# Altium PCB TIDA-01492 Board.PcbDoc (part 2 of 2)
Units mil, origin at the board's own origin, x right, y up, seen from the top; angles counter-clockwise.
Board outline 4930.03 x 2625.03 mil, 4 copper layers (Top Layer, Signal Layer 1, Signal Layer 2, Bottom Layer), stack 38.4 mil thick; 141 components, 49 nets, 383 pads, 426 vias.
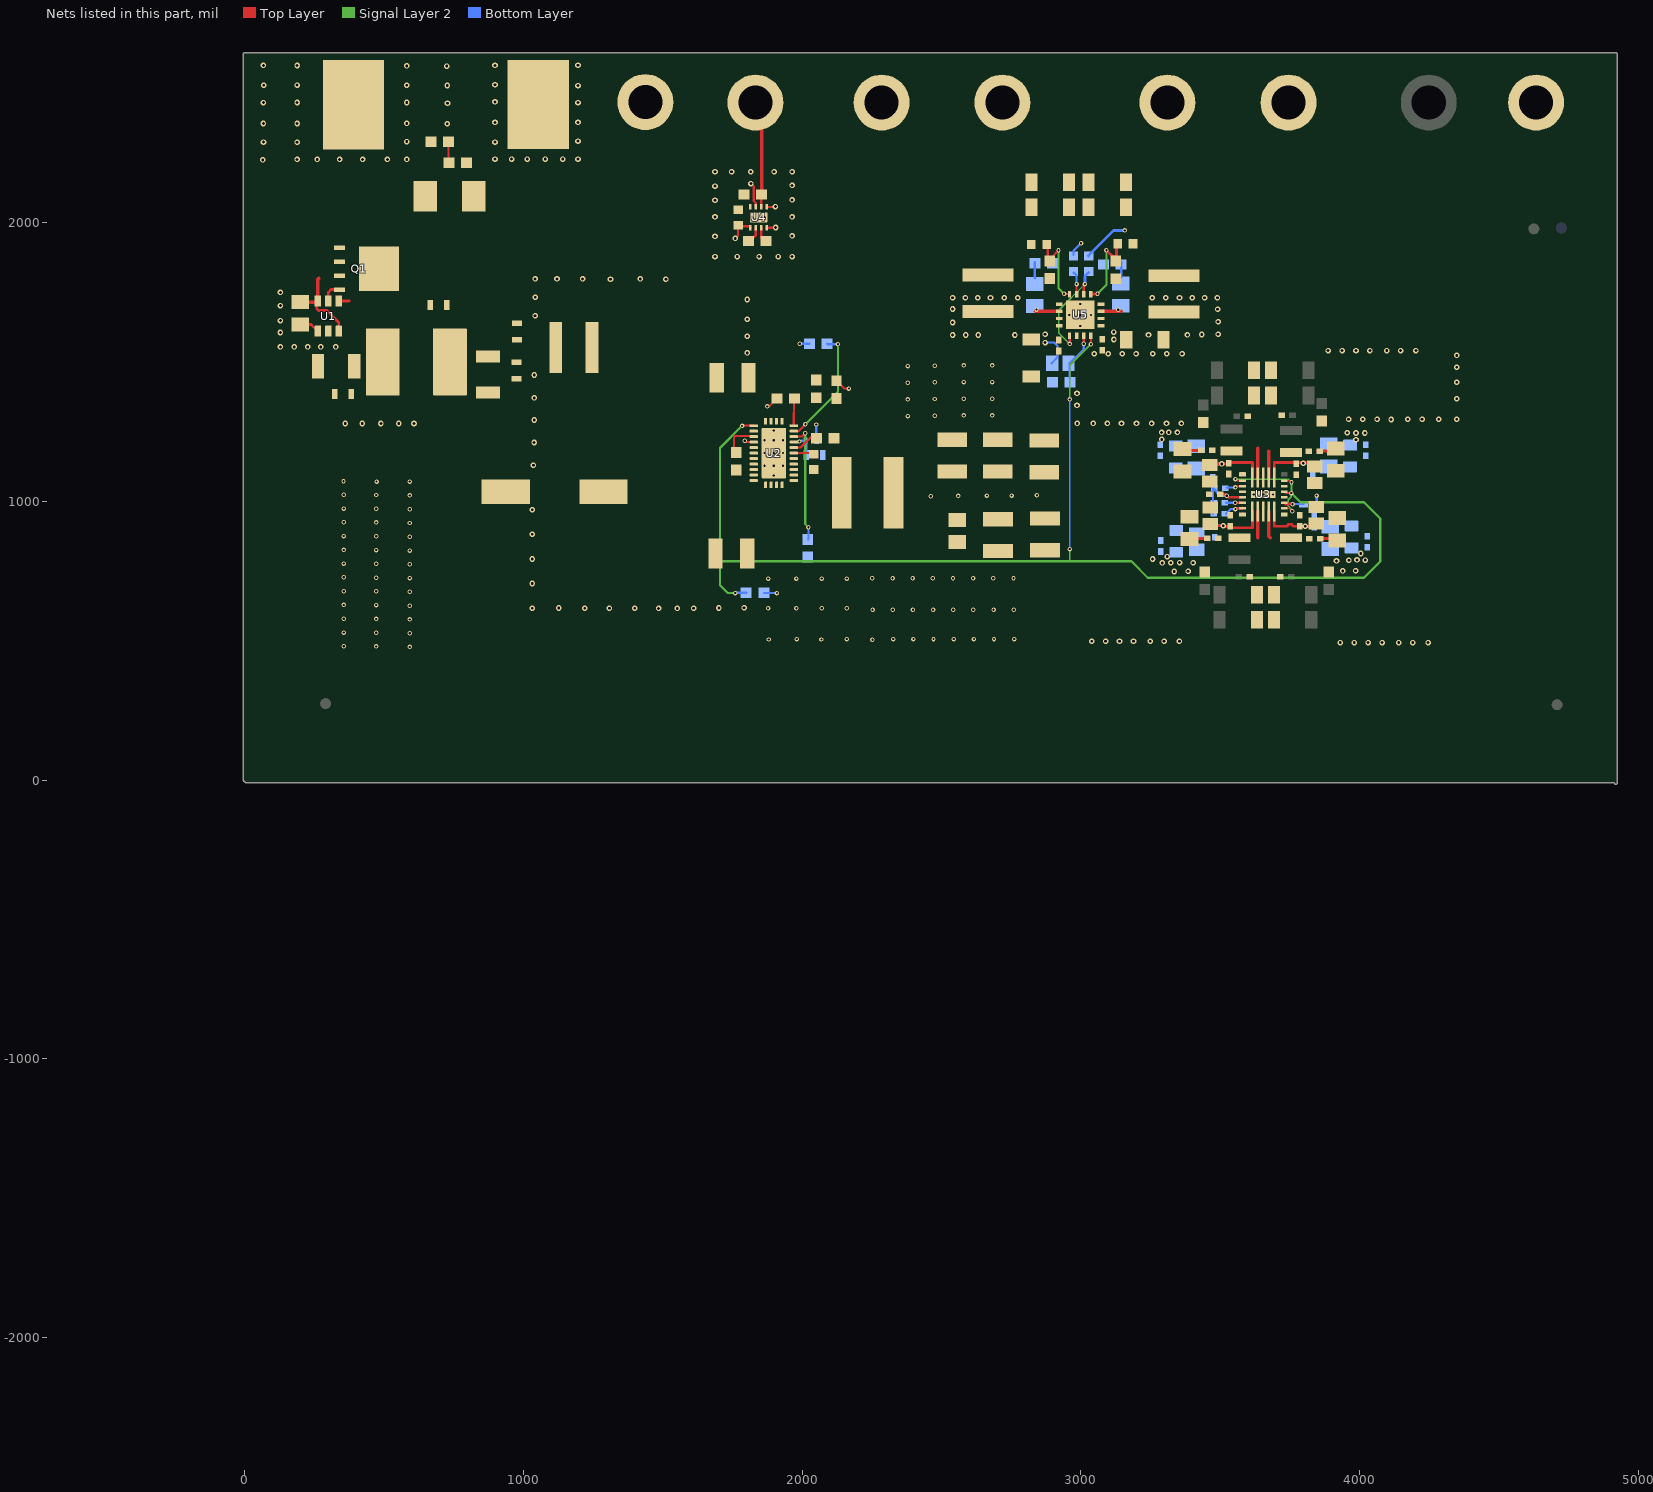
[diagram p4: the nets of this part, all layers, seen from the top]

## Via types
v1: diameter 20, hole 10, Top Layer to Bottom Layer, 270 vias
v2: diameter 16, hole 8, Top Layer to Bottom Layer, 134 vias
v3: diameter 19.68, hole 7.87, Top Layer to Bottom Layer, 21 vias
v4: diameter 16/16/16/16 (per signal layer), hole 8, Top Layer to Bottom Layer, 1 vias

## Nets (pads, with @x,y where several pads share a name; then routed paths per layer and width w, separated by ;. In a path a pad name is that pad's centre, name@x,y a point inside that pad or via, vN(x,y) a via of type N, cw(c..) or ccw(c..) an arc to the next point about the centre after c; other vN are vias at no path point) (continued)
1.2V: 1.2V.1 C56.1 C57.1 L11.2 R14.2
1.8V: 1.8V.1 C54.1 C55.1 L10.2 R11.1 R12.2 | length 169.2
  Bottom Layer w10: R11.1@3028,1880.56 3028,1882.5 3118,1972.5 v2(3158,1972.5)
5V_CAN: 5V.1 C47.1 U4.6 | length 384.7
  Top Layer w10: U4.6@1853.69,2056.75 1853.69,2100.19 C47.1@1855.35,2101.85
  Top Layer w13: 5V.1@1832.5,2431 1854.84,2408.66 C47.1@1854.84,2101.35
AGND: CSS.2 NTGND.2 RFBB.1 U2.19 | length 120.9
  Top Layer w8: v4(1794.5,1217.5) 1799.13,1212.87 U2.19@1826.65,1212.87 ; v2@1878.5,1344.5 v2(1875,1341) 1881.99,1341 RFBB.1@1910.19,1369.2
  Bottom Layer w8: v2(1991.5,1566) CSS.2@2026.5,1566
BIAS: Cbias1.1 Rbias1.1 U2.8 | length 63.3
  Bottom Layer w8: v2(1990.5,1215) 1993.5,1218 Rbias1.1@2012.5,1218 2015,1215.5 Cbias1.1@2015,1179
FB: CFF.2 RFBB.2 RFBT.1 U2.11 | length 97.1
  Top Layer w8: U2.11@1970.35,1271.93 RFBB.2@1970.5,1369
FB1_: R12.1 R15.2 U5.5 | length 285.6
  Top Layer w10: U5.5@3036.14,1744.01 3059.01,1744.01 v2(3060,1745) ; v2(3092,1901) 3114.5,1878.5 3129,1878.5 3128.5,1878.99 R12.1@3128.5,1924
  Signal Layer 2 w8: v2(3060,1745) 3092,1777 v2(3092,1901)
FB2_: R14.1 R17.2 U5.8 | length 277.9
  Top Layer w8: R14.1@2881.5,1922 2881.5,1877 2882,1876.5 2895.5,1876.5 v2(2920,1901) ; v2(2940,1745) 2940.99,1744.01 U5.8@2959.36,1744.01
  Signal Layer 2 w8: v2(2920,1901) 2920,1765 v2(2940,1745)
GATEDRIVE: Q1.4 U1.5 | length 74.6
  Top Layer w10: U1.5@300,1719.13 300,1750 310,1760 Q1.4@339.57,1760
GND: C0_2.1 C0_3.2 C1.2 C1_2.1 C1_3.2 C2.2 C2_2.1 C2_3.2 C3.2 C3_2.1 C3_3.2 C4.2 C5.1 C6.2 C7.1 C8.2 C10.1 C18.2 C19.2 C20.1 C21.2 C22.2 C23.1 C26.2 C27.2 C28.1 C29.2 C30.2 C31.1 C32.2 C33.2 C34.1 C35.2 C36.2 C37.2 C38.1 C39.2 C40.2 C41.2 C42.2 C43.2 C44.2 C45.2 C47.2 C48.2 C49.1 C50.2 C51.1 C52.2 C53.2 C54.2 C55.2 C56.2 C57.2 C58.2 Cbias1.2 Cbulk1.2 CF1.2 CF2.2 CI1.1 CI2.1 CI3.1 CO1.2 CO2.2 CO3.2 CO4.2 CO5.2 CO.1 CVCC.2 D1.2 GND1.1 GND2.1 GND3.1 GND4.1 GND_.1 NTGND.1 R1.1 R2.1 R3.1 R4.1 R15.1 R17.1 RT.2 U1.2 U2.12 U2.13 U2.14 U2.15 U2.17 U2.23 U2.24 U2.25 U2.26 U2.27 U2.28 U2.29 U2.30 U2.31 U3.1 U3.4 U3.6 U3.11 U3.14 U3.17 U3.21 U3.24 U3.27 U4.8 U4.9@1843.84,2019.35 U5.4 U5.9 U5.14 U5.17 | length 2.3
  Top Layer w10: U3.21@3580.2,953.15 U3.21@3580.2,955.43
  other v1: 3931,493.5 3981,493.5 4031,493.5 4081,493.5 4141,493.5 4191,493.5 4246,493.5 3039,498 3089,498 3139,498 3189,498 3249,498 3299,498 3354,498 1308.5,616.5 1399.5,616.5 1485,616 1552,616 1032,617 1220,617 1610.5,617 1126.5,617.5 1701.5,617.5 1792,618.5 1032,705.5 3335.5,748.5 3385,749.5 3940,750.5 3986,751 3403,780 3917.5,786.5 1032,793.5 3257.5,793.5 1032,882 1032,970 1036,1129.5 1038.5,1211.5 360.5,1279.5 421.5,1279.5 488.5,1279.5 553,1279.5 607.5,1279.5 2987,1280 3044.5,1280 3095.5,1280 3146,1280 3200,1280 3254,1280 3307.5,1280 3361,1280 1039,1292 3961,1294.5 4012,1294.5 4063,1294.5 4113.5,1294 4173,1294.5 4224.5,1294.5 4284.5,1294.5 4349,1294.5 2986.5,1344.5 4349,1368.31 1039,1371.5 2986.5,1387.5 4349,1427.81 1039,1453.5 4349,1481.31 4349,1524 3048.5,1529.5 3098.5,1529.5 3148.5,1529.5 3198.5,1529.5 3258.5,1529.5 3308.5,1529.5 3363.5,1529.5 1803.5,1533 3887.5,1541 3937.5,1541 3987.5,1541 4037.5,1541 4097.5,1541 4147.5,1541 4202.5,1541 128,1554.5 177.5,1554.5 226,1554.5 273,1554.5 327,1554.5 1803.5,1593 2540,1597 2587.5,1597 2632,1597 2763.5,1597 3243,1597.5 3382.5,1597.5 3434,1599 3492.5,1599.5 128,1606 2540,1642 3492.5,1645 128,1649 1803,1653.5 1042,1666 2540,1690.5 3491,1689.5 128,1702.5 1803,1724.5 2540,1730.5 2586,1730.5 2630,1730.5 2676,1730.5 2725.71,1730.5 2774,1730.5 3256.26,1730.57 3304.54,1730.57 3354.26,1730.57 3400.26,1730.57 3444.26,1730.57 3490.26,1730.57 1042.5,1732.5 128,1750 1042,1798.5 1120.5,1798.5 1212.5,1798.5 1312.5,1797.5 1419,1798.5 1511.5,1797.5 1687.5,1878.5 1767.5,1878.5 1845.5,1878.5 1914.5,1878.5 1964,1878.5 1687.5,1951 1964,1952.5 1687.5,2021 1964,2021 1687.5,2081 1964,2082 1687.5,2131.5 1964,2134 1687.5,2183 1747,2183 1815.5,2183 1899.5,2183 1964,2183 64.5,2225.5 898,2228.5 957.5,2228.5 1014,2228.5 1078.5,2228.5 1141,2228.5 1196,2228.5 67.5,2289.5 898,2289.5 1196,2293 726.5,2355 67,2356 898,2360 1196,2360 727.5,2429 67,2431 1196,2431 898,2433.5 726.5,2492.5 1196,2492 68,2493.5 898,2495 725,2562 67,2564.5 898,2564.5 1196,2565
  other v2: 592.5,478 355.5,480.5 472,479.5 1880,504.5 2069.5,504.5 2252.5,504 1980.5,506 2160.5,506 2327,506 2399.5,506 2471.5,506 2544,506 2616.5,506 2688.5,506 2761,506 592.5,527 472,529 355.5,529.5 592.5,576.5 472,578.5 355.5,579 2253,611 2325,611 2397.5,611 2470,611 2542,611 2614.5,611 2687,611 2759.5,611 1878,617 1979.5,617 2070.5,617 2160.5,617 592.5,626 355.5,628.5 472,628 592.5,675.5 355.5,678 472,677.5 1878.5,723 1979.5,723 2070.5,723 2160.5,723 2252,724 2324.5,724 2396.5,724 2469,724 2541.5,724 2613.5,724 2686,724 2758.5,724 592.5,725 472,726.5 355.5,727.5 592.5,774.5 472,776 355.5,777 592.5,823.5 355.5,826 472,825.5 592.5,873 472,875 355.5,875.5 592.5,922.5 472,924.5 355.5,925 592.5,972 355.5,974.5 472,974 592.5,1021.5 472,1023 355.5,1024 473,1071 592.5,1071 354.5,1072 2379,1306 2476,1307.5 2580,1308.5 2682.5,1308.5 2379,1366 2476,1367.5 2580,1368.5 2682.5,1368.5 2379,1426 2476,1427.5 2580,1428 2682.5,1428 2379,1485.5 2476,1487 2580,1488 2682.5,1488
  other v3: 3620.75,1025 3655,1025 3689.25,1025 1898.5,1092.79 1865.04,1127.83 1898.5,1127.83 1931.96,1127.83 1865.04,1173.5 1898.5,1173.5 1931.96,1173.5 1865.04,1219.17 1898.5,1219.17 1931.96,1219.17 1898.5,1254.21 2997.75,1629.84 2958.38,1669.21 2997.75,1669.21 3037.12,1669.21 2997.75,1708.58 1822.19,2019.35 1865.5,2019.35
NetC3_1: C3.1 C8.1 CF2.1 FB1.2 LF1.1
NetC9_2: C9.2 C10.2 | length 75.8
  Top Layer w8: C9.2@731.5,2290 731.5,2217.01 C10.2@733.5,2215
NetC11_2: C11.2 U1.1 | length 72.6
  Top Layer w10: C11.2@200,1635 238.46,1635 U1.1@262.6,1610.87
NetC16_2: C16.2 R1.2 | length 69.7
  Top Layer w6: R1.2@3905.5,1180.5 R1.2@3915,1190
  Top Layer w10: C16.2@3849.19,1180.5 R1.2@3905.5,1180.5
NetC17_2: C17.2 R2.2 | length 67.4
  Top Layer w10: C17.2@3855.49,867.09 3912.91,867.09 R2.2@3920,860
NetC24_2: C24.2 R3.2 | length 69.7
  Top Layer w10: R3.2@3365,1187.5 3369.5,1183 C24.2@3432.81,1183
NetC25_2: C25.2 R4.2 | length 65.1
  Top Layer w10: R4.2@3390,865 3392,867 C25.2@3454.31,867
NetC46_1: C46.1 U4.3 | length 59.5
  Top Layer w10: U4.3@1853.69,1981.94 1853.69,1946 C46.1@1870.34,1929.35
NetC46_2: C46.2 U4.2 | length 63.6
  Top Layer w10: C46.2@1807.35,1929.35 1834,1956 U4.2@1834,1981.94
NetC52_1: C52.1 R10.2 | length 54.5
  Bottom Layer w10: R10.2@3145,1805 C52.1@3145,1859.5
NetC58_1: C58.1 R16.1 | length 56.9
  Bottom Layer w10: C58.1@2835,1858.5 2835,1803 R16.1@2836,1802
NetCB_1: CB.1 U2.6 | length 60.7
  Top Layer w8: U2.6@1970.35,1173.5 CB.1@2031,1173.5
NetR5_2: R5.2 U3.16 | length 61.3
  Top Layer w6: v2(3555,1050) 3559.53,1054.53 U3.16@3580.2,1054.53
  Bottom Layer w6: R5.2@3521.62,1048 3523.62,1050 v2(3555,1050)
NetR6_2: R6.2 U3.3 | length 72
  Top Layer w10: U3.3@3729.8,995.47 3734.57,990.71 3759.29,990.71 v2(3760,990)
  Bottom Layer w8: v2(3760,990) 3760.5,990.5 R6.2@3799.38,990.5
NetR7_2: R7.2 U3.20 | length 69.1
  Top Layer w8: v2(3555,972.5) 3558.29,975.79 U3.20@3580.2,975.79 U3.20@3580.2,976.87
  Bottom Layer w8: R7.2@3520.62,955.5 3537.62,972.5 v2(3555,972.5)
NetR8_2: R8.2 U3.19 | length 59.1
  Top Layer w8: v2(3554,995.5) U3.19@3580.2,995.47
  Bottom Layer w8: R8.2@3521.12,995.5 v2(3554,995.5)
NetR11_2: R11.2 U5.6 U5.13 | length 383.6
  Top Layer w8: v2(2960,1565) U5.13@2960,1593.77
  Top Layer w10: U5.6@3010.54,1744.01 3010.54,1775.54 v2(3015,1780)
  Signal Layer 2 w6: v2(2960,1565) 2921,1604 2921,1686 v2(3015,1780)
  Bottom Layer w10: v2(3015,1780) 3015,1808.5 R11.2@3028,1821.5
NetR13_2: R13.2 U5.7 | length 82.1
  Top Layer w8: U5.7@2984.95,1744.01 v2(2985,1780) v2(2985,1780)
  Bottom Layer w8: R13.2@2974,1821.5 2985,1810.5 v2(2985,1780)
NetRPG_1: RPG.1 U2.16 U3.2 U3.5 U3.7 U3.15 U5.16 | length 4961.9
  Top Layer w6: v2(3555,1080) 3560.79,1074.21 U3.15@3580.2,1074.21 ; U3.2@3729.8,975.79 3747.21,975.79 v2(3758.5,964.5) ; U3.5@3729.8,1034.84 3734.65,1030 v2(3755,1030) ; U3.7@3729.8,1074.21 3750.79,1074.21 v2(3756,1069)
  Top Layer w8: v2(1784.5,1271) 1785.43,1271.93 U2.16@1826.65,1271.93 ; v2(3036.14,1563.86) U5.16@3036.14,1594.41
  Signal Layer 2 w6: v2(2960.14,1366.14) 2960.5,1488 v2(3036.14,1563.86) ; 2960.5,785 v2(2960.5,829) ; v2(3555,1080) 3745,1080 v2(3756,1069) 3756,1031 v2(3755,1030) 3755,1017 3744,1006 3744,983.37 3758.5,968.87 v2(3758.5,964.5)
  Signal Layer 2 w8: v2(1760,671) 1733,671 1705,699 1705,785 ; v2(1784.5,1271) 1705,1191.5 1705,785 ; v2(3755,1030) 3788.04,996.96 4016.5,997 4074.5,939 4074.5,784.5 4016.5,726.5 3240.5,726.5 3182,785 1705,785
  Bottom Layer w6: v2(2960.14,1366.14) v2(2960.5,829)
  Bottom Layer w8: v2(1760,671) 1761.5,672.5 RPG.1@1799.5,672.5
RT: RT.1 U2.9 | length 432.3
  Top Layer w8: U2.9@1970.35,1232.56 1999.56,1232.56 v2(2011.5,1244.5)
  Signal Layer 2 w8: v2(2011.5,1244.5) 2011.5,918.5 v2(2022.5,907.5)
  Bottom Layer w8: RT.1@2021,863.5 2022.5,865 v2(2022.5,907.5)
SS/TRK: CSS.1 U2.10 | length 427.2
  Top Layer w8: U2.10@1970.35,1252.24 1986.97,1252.24 v2(2012,1277.27)
  Signal Layer 2 w8: v2(2012,1277.27) 2128.5,1393.77 v2(2128.5,1564)
  Bottom Layer w8: v2(2012,1277.27) v2@2012.23,1277.5 ; CSS.1@2089.5,1566 2091.5,1564 v2(2128.5,1564)
SW: CB.2 L1.1 U2.1 U2.2 U2.3 U2.4 U2.5
SW1_: L10.1 R10.1 U5.3 | length 72.4
  Top Layer w13: U5.3@3072.55,1682.01 3144.95,1682.01
  other v2: 3134,1688
SW2_: L11.1 R16.2 U5.10 | length 85.9
  Top Layer w13: v2@2837.01,1682.01 U5.10@2922.95,1682.01
  other v2: 2841,1688.5
SW_0: C16.1 L6.1 U3.10 | length 94.1
  Top Layer w13: U3.10@3674.69,1085.63 3674.69,1179.69
SW_1: C24.1 L7.1 U3.12 | length 104.1
  Top Layer w13: U3.12@3635.31,1085.63 3635.31,1189.68
SW_2: C17.1 L8.1 U3.25 | length 96.6
  Top Layer w13: U3.25@3674.69,964.37 3674.69,875.31 3680,870
SW_3: C25.1 L9.1 U3.23 | length 94.5
  Top Layer w13: 3635,870 3635.31,870.32 U3.23@3635.31,964.37
V2: C18.1 C21.1 C26.1 C29.1 C44.1 C45.1 C48.1 C49.2 C50.1 C51.2 CFF.1 CO1.1 CO2.1 CO3.1 CO4.1 CO5.1 CO.2 L1.2 L2.1 L3.1 L4.1 L5.1 R5.1 R6.1 R7.1 R8.1 R9.1 R13.1 Rbias1.2 RFBT.2 RPG.2 U3.18 U4.1 U4.4 U4.5 U4.7 U5.1 U5.2 U5.11 U5.12 | length 849.8
  Top Layer w8: v1(1760.32,1943.75) 1770.32,1953.75 1770.32,1987.25 1809.01,1987.25 U4.1@1814.32,1981.94 ; v1(1816.32,2140.25) 1826.15,2130.42 1826.15,2078.92 1834,2071.07 U4.7@1834,2056.75 ; U4.4@1873.37,1981.94 1904.02,1981.94 v1(1904.82,1982.75) ; U4.5@1873.37,2056.75 1903.32,2056.75 v1(1904.32,2057.75) ; RFBT.2@2123.5,1433 2151.5,1405 v2(2168,1405) ; v2(3523.5,1020.5) 3528.84,1015.16 U3.18@3580.2,1015.16
  Top Layer w10: C44.1@3499.69,1025 3519,1025 v2(3523.5,1020.5)
  Bottom Layer w8: RPG.2@1864,671 v2(1909.5,671) ; v2(2050.5,1276) 2050.5,1220 Rbias1.2@2052.5,1218 ; v1(2872,1570) 2905,1570 2916,1559 2916,1516.5 R9.1@2895.5,1496 ; R13.1@2974,1884.5 2974,1899 v2(3001,1926) ; R7.1@3473.38,955.5 3473.38,995 3473.88,995.5 3474.38,996 R5.1@3474.38,1048 ; v2(3846,1021) 3846.62,1020.38 R6.1@3846.62,990.5
  Bottom Layer w10: R5.1@3474.38,1048 3501.88,1020.5 v2(3523.5,1020.5)
  other v1: 3292.5,779.5 3322.5,780 3354.5,780.5 3962,789 3991,790 4020.5,789.5 3310,802 4004.5,813 3987.5,1221 3290.5,1222.5 3956,1246 3987.5,1245.5 4019.5,1245.5 3290,1247.5 3315.5,1247.5 3346.5,1247.5 3119,1581 2872,1600 3118.5,1607.5
  other v2: 2461.5,1018.5 2560,1019.5 2663,1021 2751.5,1021 2842.5,1022
VCC: CVCC.1 U2.7 | length 95.9
  Top Layer w8: U2.7@1970.35,1193.18 1994.3,1193.18 2039.62,1238.5 CVCC.1@2047.5,1238.5
VIN: C9.1 C11.1 D1.1 IN.1 Q1.1 Q1.2 Q1.3 U1.3 U1.6 | length 300.6
  Top Layer w10: U1.6@258.46,1715 258.46,1691.54 265,1685 295,1685 337.4,1642.6 U1.3@337.4,1610.87
  Top Layer w13: C11.1@200,1715 258.46,1715 U1.6@262.6,1719.13 262.6,1797.6 265,1800
  other v1: 188,2227 260.5,2227 340.5,2227 423,2227 512,2227 581.5,2227 188,2288.5 581.5,2291 188,2356 581.5,2356.5 188,2431.5 581.5,2431.5 188,2494 581.5,2493.5 581.5,2562.5 188,2564
VIN1: Cbulk1.1 CI1.2 CI2.2 CI3.2 LF1.2 U2.18 U2.20 U2.21 U2.22 | length 135.9
  Top Layer w8: CI1.2@1763.5,1175 1755.5,1183 1755.5,1234.5 1826.65,1234.5 U2.18@1826.65,1232.56
VIN2: C1.1 C2.1 CF1.1 FB1.1 Q1.5 U1.4 | length 38
  Top Layer w10: U1.4@337.4,1719.13 374.13,1719.13 375,1720
VINB0: C4.1 C19.1 C20.2 C34.2 L2.2 U3.9 | length 241.9
  Top Layer w10: U3.9@3694.37,1085.63 3694.37,1139.37 3825.16,1139.37 C4.1@3840,1124.53
  Bottom Layer w10: v1(3798,1137) 3829.69,1137 C20.2@3833,1133.69
VINB1: C5.2 C27.1 C28.2 C35.1 L4.2 U3.13 | length 237
  Top Layer w10: C5.2@3470,1129.53 3475.16,1134.68 v1(3506,1134.68) C35.1@3530,1134.68 ; C35.1@3529.84,1139.37 3615.63,1139.37 U3.13@3615.63,1085.63
  Bottom Layer w10: C28.2@3474,1126.69 3482,1134.68 v1(3506,1134.68)
VINB2: C6.1 C22.1 C23.2 C38.2 L3.2 U3.26 | length 223.7
  Top Layer w10: U3.26@3694.37,964.37 3694.37,910.63 3739.09,910.63 3746.33,917.87 3755.6,917.87 3762.84,910.63 v1(3805.16,910.63) C6.1@3824.5,910.63
  Bottom Layer w10: v1(3805.16,910.63) 3835.69,910.63 C23.2@3838,908.31
VINB3: C7.2 C30.1 C31.2 C39.1 L5.2 U3.22 | length 254.6
  Top Layer w10: C7.2@3465,919.47 3471.47,913 v1(3511,913) 3513.69,910.32 C39.1@3536,910.32 3540.69,905.63 3615.63,905.63 U3.22@3615.63,964.37
  Bottom Layer w10: C31.2@3473,909.31 3476.69,913 v1(3511,913)
VINC: C53.1 R9.2 U5.15 | length 172.6
  Top Layer w8: v2(3010.54,1565.54) U5.15@3010.54,1594.41
  Bottom Layer w8: C53.1@2959.5,1443 2959.5,1495 3010.54,1546.05 v2(3010.54,1565.54)
pads on no net: FID1.1 FID2.1 FID3.1 FID4.1 FID5.1 FID6.1 U2.31A U3. U4.9@1826.13,2019.35 U4.9@1861.56,2019.35
copper on no net: | length 280
  Top Layer w10: -610,-2370 -330,-2370

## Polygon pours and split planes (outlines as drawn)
V2 on Top Layer "TOP_LAYER_V2_P140" (solid, remove dead copper, pour order 140): 2246.69,1164.33 2946.01,1164.33 2946.01,896.91 2245.44,896.91
SW on Top Layer "TOP_LAYER_SW_P142" (solid, remove dead copper, pour order 142): 1955.2,1159 2176.5,1159 2176.5,889.5 2106.5,889.5 2106.5,1069.5 1955.2,1069.5
VIN1 on Top Layer "TOP_LAYER_VIN1_P150" (solid, remove dead copper, pour order 150): 1757.41,1201.31 1847.56,1201.81 1847.56,1146.37 1757.41,1146.37
VIN1 on Top Layer "TOP_LAYER_VIN1_P158" (solid, remove dead copper, pour order 158): 1199.1,1769 1199.1,659.5 1720.5,659.5 1720.5,1769
0.9V on Top Layer "TOP_LAYER_0.9V_P214" (solid, remove dead copper, pour order 214): 3585,1235 3500,1235 3500,1310 3015,1310 3015,1510 3575,1510 3575,1285 3585,1285
0.9V on Top Layer "TOP_LAYER_0.9V_P182" (solid, remove dead copper, pour order 182): 3715,1235 3795,1235 3795,1330 4315,1330 4315,1510 3745,1510 3745,1285 3715,1285
SW_3 on Top Layer "TOP_LAYER_SW_3_P164" (solid, remove dead copper, pour order 164): 3481,848 3640,848 3640,890 3481,890
SW_2 on Top Layer "TOP_LAYER_SW_2_P216" (solid, remove dead copper, pour order 216): 3835.8,850 3670,850 3670,890 3835.8,890
SW_0 on Top Layer "TOP_LAYER_SW_0_P212" (solid, remove dead copper, pour order 212): 3830,1205 3670,1205 3670,1155 3830,1155
SW_1 on Top Layer "TOP_LAYER_SW_1_P210" (solid, remove dead copper, pour order 210): 3460,1205 3640,1205 3640,1160 3460,1160
V2 on Top Layer "TOP_LAYER_V2_P188" (solid, remove dead copper, pour order 188): 3060,1665 3105,1665 3105,1620 3200,1620 3200,1535 3167.5,1567.5 3060.35,1567.5
0.9V on Top Layer "TOP_LAYER_0.9V_P194" (solid, remove dead copper, pour order 194): 3610,810 3530,810 3530,715 3010,715 3010,535 3580,535 3580,760 3610,760
0.9V on Top Layer "TOP_LAYER_0.9V_P192" (solid, remove dead copper, pour order 192): 3715,810 3815,810 3815,720 4315,720 4315,535 3740,535 3740,760 3715,760
V2 on Top Layer "TOP_LAYER_V2_P196" (solid, remove dead copper, pour order 196): 2935,1665 2935,1559.5 2791,1559.5 2791,1620 2875,1620 2875,1665
SW1_ on Top Layer "TOP_LAYER_SW1__P200" (solid, remove dead copper, pour order 200): 3449.67,1625.94 3293.42,1625.94 3107.75,1625.94 3107.75,1705 3450.27,1705
SW2_ on Top Layer "TOP_LAYER_SW2__P202" (solid, remove dead copper, pour order 202): 2867.75,1705 2570,1705 2570,1629.21 2867.75,1629.21 2867.75,1659.21
1.8V on Top Layer "TOP_LAYER_1.8V_P204" (solid, remove dead copper, pour order 204): 3472,1784 3237,1784 3237,1860.99 3137,1860.99 3137,2583.5 3472,2583.5
1.2V on Top Layer "TOP_LAYER_1.2V_P186" (solid, remove dead copper, pour order 186): 2569.75,1780.75 2801.13,1780.75 2801.13,1860.75 2852.5,1860.75 2852.5,2584.25 2569.75,2584.25
GND on Top Layer "TOP_LAYER_GND_P218" (solid, remove dead copper, pour order 218): -4.95,2595.72 0.05,2600.72 4915.05,2600.72 4915.05,-14.28 -9.95,-14.28
VIN2 on Top Layer "TOP_LAYER_VIN2_P170" (solid, remove dead copper, pour order 170): 365.11,1680.89 365.11,1310.93 580.11,1310.8 580.11,1680.89
no net on Top Layer "TOP_LAYER_NONET_P168" (solid, remove dead copper, pour order 168): 659.24,1605 1023.59,1605 1023.59,1525 659.24,1525
VIN on Top Layer "TOP_LAYER_VIN_P160" (solid, remove dead copper, pour order 160): 120.25,2585.14 120.25,1985.01 690.75,1985.01 690.75,2584.64
VIN1 on Top Layer "TOP_LAYER_VIN1_P134" (solid, remove dead copper, pour order 134): 1775,1201.79 1707.5,1201.79 1707.5,1146.5 1774.5,1146.5
GND on Signal Layer 1 "SIGNAL_LAYER_1_GND_P190" (solid, remove dead copper, pour order 190): 20.47,2584.53 4899.53,2584.53 4899.53,0 20.47,0
AGND on Signal Layer 2 "SIGNAL_LAYER_2_AGND_P136" (solid, remove dead copper, pour order 136): 1782.85,1206.7 1782.85,1236.3 1852.1,1305.55 1852.94,1600.52 2045.32,1600.02 2045.32,1444.33 1852.04,1251.05 1825.54,1224.55 1825.54,1207.3
GND on Signal Layer 2 "SIGNAL_LAYER_2_GND_P206" (solid, remove dead copper, pour order 206): 20.47,2584.53 20.47,15.47 4899.53,15.47 4899.53,2577.01
V2 on Signal Layer 2 "SIGNAL_LAYER_2_V2_P166" (solid, remove dead copper, pour order 166): 1628.07,2159.5 1628.07,523.8 4323.07,523.8 4323.07,2159.5
GND on Bottom Layer "BOTTOM_LAYER_GND_P208" (solid, remove dead copper, pour order 208): -5.02,2660 -5.02,-10 4914.98,-10 4914.98,2660
0.9V on Bottom Layer "BOTTOM_LAYER_0.9V_P174" (solid, remove dead copper, pour order 174): 3000.12,1499.67 3236,1499.67 3236,531.16 3003.63,531.16 3000.12,534.67
0.9V on Bottom Layer "BOTTOM_LAYER_0.9V_P172" (solid, remove dead copper, pour order 172): 4124.4,2584 4390.64,2584 4390.64,531.14 4124.4,531.14
0.9V on Bottom Layer "BOTTOM_LAYER_0.9V_P176" (solid, remove dead copper, pour order 176): 3005,725 3005,536.49 3006.49,535 4286.49,535 4286.49,730 4286.09,729.59 3006.9,729.59
no net on Bottom Layer "BOTTOM_LAYER_NONET_P180" (solid, remove dead copper, pour order 180): 3050,1445 3050,1256.49 3051.49,1255 4331.49,1255 4331.49,1450 4331.09,1449.59 3051.9,1449.59
0.9V on Bottom Layer "BOTTOM_LAYER_0.9V_P178" (solid, remove dead copper, pour order 178): 3005,1500 3005,1311.49 3006.49,1310 4286.49,1310 4286.49,1505 4286.09,1504.59 3006.9,1504.59

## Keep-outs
Keep-Out Layer:
  lines w10: -5,-10 -5,55 -5,2195 -5,2605 4925,2610 4920,-10 4685,-10 -5,-10

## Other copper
Top Layer:
  rectangle net V2: 2029.5,1414 2143,1455
  rectangle net FB: 1952.5,1344.32 2148.2,1394
  rectangle net VIN2: 365,1670 690,1980
  rectangle net VIN: 120,1780 360,2050
  rectangle net NetC3_1: 681.5,1484.5 1137,1600
Bottom Layer:
  rectangle net VINB2: 3828,897 3993.5,920.5
  rectangle net V2: 3947.5,771.5 4048.5,846.5
  rectangle net VINB0: 3825.16,1120 3990.5,1139.37
  rectangle net V2: 3942,1192.5 4047,1265
  rectangle net VINB3: 3320,898 3482.5,914.5
  rectangle net V2: 3278.01,764 3373,838
  rectangle net VINB1: 3321.5,1115 3480.5,1133.5
  rectangle net V2: 3274.5,1182 3366.5,1263.5
  rectangle net V2: 3274.5,1209.5 3275,1211.5

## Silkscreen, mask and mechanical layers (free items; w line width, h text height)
Top Overlay:
  region: 3522,246 3222,246 3222,146 3522,146
  text "TIDA-01492" at 3634,171 h108.27
  text ".Layer_Name" at 567,-1698.49 h60
Bottom Overlay:
  text ".Layer_Name" at 567,-1698.49 h60
M1 Board Outline:
  lines w10: 0,0 5,-5 4915,-5 4920,-10 4920,2605 0,2605 0,0
  text ".Layer_Name" at 567,-1698.49 h60
M2 Board Dimensions:
  rectangle: -10,-1115 115,-990
  rectangle: 115,-1240 490,-1115
  lines w7: -10,-1115 990,-1115 ; 115,-1240 115,-990 ; 240,-1240 240,-990 ; 490,-1240 490,-990 ; 740,-1240 740,-990 ; -10,-1240 990,-1240 990,-990 -10,-990 -10,-1240
  text ".Layer_Name" at 567,-1698.49 h60
M3 3D STEP Top:
  text ".Layer_Name" at 567,-1698.49 h60
M4 3D STEP Bottom:
  text ".Layer_Name" at 567,-1698.49 h60
M5 Assembly Top:
  lines w10: -302,-1770.17 6298,-1770.17 ; -302,-1566.83 6300,-1566.83 ; -302,-1363.5 -302,-1973.5 3703,-1973.5 6300,-1973.5 6300,-1363.5 -301.5,-1363.5 -301.5,-1973.5 1274,-1973.5 ; 2163,-1973.5 2163,-1363.5 ; 3430,-1566.83 3430,-1363.5 ; 4270,-1566.83 4270,-1363.5 ; 4892,-1980 4892,-1777.17
  text "COMPONENTS MARKED 'DNP' SHOULD NOT BE POPULATED." at 1143.5,-1158.5 h60
  text "ASSEMBLY VARIANT:" at 1143,-1274 h60
  text ".VariantName" at 2179,-1274 h60
  text "PCB VIEWED FROM TOP SIDE" at -238.5,-1495.67 h60
  text "BOARD #:" at 2238,-1495.67 h60
  text ".PRJ_Number" at 2783.5,-1495.67 h60
  text "REV:" at 3628,-1495.67 h60
  text ".PCB_Rev" at 3919.5,-1495.67 h60
  text "SVN REV:" at 4466,-1495.67 h60
  text ".VersionControl_RevNumber" at 4972,-1495.67 h60
  text "TID #:" at 2238,-1699 h60
  text ".TID" at 2783.5,-1699 h60
  text "PLOT NAME =" at -238.5,-1904.34 h60
  text ".plot_File_Name" at 567,-1904.34 h60
  text "GENERATED    :" at 2240,-1904.34 h60
  text ".Print_Date" at 3109.5,-1904.34 h60
  text ".Print_Time" at 3838.5,-1904.34 h60
  text "TEXAS INSTRUMENTS" at 5103,-1904.34 h60
M6 Assembly Bottom:
  lines w10: -302.5,-1567.33 6299.5,-1567.33 ; -300.5,-1770.67 6299.5,-1770.67 ; 1105.5,-1980.5 1105.5,-1777.67 ; 1727.5,-1567.33 1727.5,-1364 ; 2567.5,-1567.33 2567.5,-1364 ; 3834.5,-1974 3834.5,-1364 ; 4723.5,-1974 6299,-1974 6299,-1364 -302.5,-1364 -302.5,-1974 2294.5,-1974 6299.5,-1974 6299.5,-1364
  text "COMPONENTS MARKED 'DNP' SHOULD NOT BE POPULATED." at 6092,-1158 h60
  text ".VariantName" at 5048,-1274 h60
  text "ASSEMBLY VARIANT:" at 6087,-1274 h60
  text ".VersionControl_RevNumber" at 1025.5,-1496.17 h60
  text "SVN REV:" at 1531.5,-1496.17 h60
  text ".PCB_Rev" at 2078,-1496.17 h60
  text "REV:" at 2369.5,-1496.17 h60
  text ".PRJ_Number" at 3214,-1496.17 h60
  text "BOARD #:" at 3759.5,-1496.17 h60
  text "PCB VIEWED FROM BOTTOM SIDE" at 6236,-1496.17 h60
  text ".TID" at 3214,-1699.5 h60
  text "TID #:" at 3759.5,-1699.5 h60
  text "TEXAS INSTRUMENTS" at 894.5,-1904.84 h60
  text ".Print_Time" at 2159,-1904.84 h60
  text ".Print_Date" at 2888,-1904.84 h60
  text "GENERATED    :" at 3757.5,-1904.84 h60
  text ".plot_File_Name" at 5430.5,-1904.84 h60
  text "PLOT NAME =" at 6236,-1904.84 h60
M9 Title Sheet:
  lines w10: -501.5,201.5 -301.5,201.5 ; -501.5,2576.5 -301.5,2576.5 ; -501.5,4951.5 -301.5,4951.5 ; 1998.5,-2173.5 1998.5,-1973.5 ; 1998.5,7126.5 1998.5,7326.5 ; 4498.5,-2173.5 4498.5,-1973.5 ; 4498.5,7126.5 4498.5,7326.5 ; 6311,-1973.5 6311,-1363.5 11293.5,-1363.5 ; 6998.5,-2173.5 6998.5,-1973.5 ; 6998.5,7126.5 6998.5,7326.5 ; 9498.5,-2173.5 9498.5,-1973.5 ; 9498.5,7126.5 9498.5,7326.5 ; 11293.5,-1973.5 11293.5,-1363.5 ; 11293.5,-1663.5 14293.5,-1663.5 ; 11293.5,-1063.5 14293.5,-1063.5 ; 11293.5,31 11293.5,-469.5 11293.5,-763.5 ; 11294.5,-469.5 14294.5,-469.5 ; 11998.5,-2173.5 11998.5,-1973.5 ; 11998.5,7126.5 11998.5,7326.5 ; 12798.5,-1963.5 12798.5,-1363.5 ; 14293.5,-1363.5 11293.5,-1363.5 ; 14293.5,-763.5 11293.5,-763.5 ; 14298.5,-773.5 14298.5,-1973.5 ; 14298.5,2576.5 14498.5,2576.5 ; 14308.03,4941.5 14508.03,4941.5 ; 11293.5,-1363.5 11293.5,-763.5 ; 14298.5,-1973.5 14298.5,7126.5 -301.5,7126.5 -301.5,-1973.5 14298.5,-1973.5 ; -501.5,-2173.5 -501.5,7326.5 14498.5,7326.5 14498.5,-2173.5 -501.5,-2173.5
  text "1" at 729.84,7196.5 h70
  text "2" at 3225.5,7196.5 h70
  text "3" at 5714.84,7196.5 h70
  text "4" at 8221.51,7196.5 h70
  text "5" at 10720.5,7196.5 h70
  text "6" at 13225.5,7196.5 h70
  text "A" at -426.5,6053.5 h70
  text "A" at 14373.5,6053.5 h70
  text "B" at -426.5,3673.5 h70
  text "B" at 14373.5,3673.5 h70
  text "C" at -426.5,1298.5 h70
  text "C" at 14373.5,1298.5 h70
  text "PROJECT TITLE:" at 11333.5,-562.5 h45
  text ".PRJ_Title" at 11383.5,-695.83 h70
  text "DESIGNED FOR:" at 11333.5,-863.5 h45
  text ".PRJ_Customer" at 11383.5,-1003.5 h70
  text "D" at -426.5,-1071.5 h70
  text "D" at 14373.5,-1071.5 h70
  text "FILE NAME:" at 11333.5,-1163.5 h45
  text ".PCB_File_Name_No_Path" at 11383.5,-1283.5 h70
  text "Texas Instruments (TI) and/or its licensors do not warrant the accuracy or completeness of this specification" at 6364,-1445.34 h45
  text "ENGINEER:" at 11333.5,-1453.5 h45
  text "LAYOUT BY:" at 12838.5,-1453.5 h45
  text "or any information contained therein. TI and/or its licensors do not warrant that this design will meet" at 6319.01,-1558 h45
  text ".PRJ_Engineer" at 11383.5,-1608.49 h70
  text ".PCB_Layout" at 12889,-1608.49 h70
  text "the specifications, will be suitable for your application or fit for any particular purpose, or will operate in" at 6319.01,-1670.67 h45
  text ".Layer_Name" at 567,-1698.49 h60
  text "ALTIUM DESIGNER VERSION:" at 12838.5,-1763.5 h45
  text "an implementation. TI and/or its licensors do not warrant that the design is production worthy. You should" at 6319.01,-1783.33 h45
  text "completely validate and test your design implementation to confirm the system functionality for your application." at 6364,-1896 h45
  text ".print_Scale" at 11383.5,-1896.83 h70
  text ".Application_BuildNumber" at 12889,-1896.83 h70
  text "1" at 729.84,-2103.5 h70
  text "2" at 3225.5,-2103.5 h70
  text "3" at 5714.84,-2103.5 h70
  text "4" at 8221.51,-2103.5 h70
  text "5" at 10720.5,-2103.5 h70
  text "6" at 13225.5,-2103.5 h70
M10 Fab Notes:
  lines w8: 11623.96,977.64 11623.96,1115.64 11761.96,1115.64 11761.96,977.64 ; 12184.46,3362.64 12184.46,3224.64 12322.46,3224.64 12322.46,3362.64 ; 12737,5156.99 12942.39,5156.99 ; 12746.53,4883 12951.92,4883 ; 12746.53,5015.99 12951.92,5015.99 ; 12991.46,3224.64 13700.46,3224.64 ; 12991.46,3537.64 13700.46,3537.64 ; 13084.96,977.64 13084.96,1115.64 13222.96,1115.64 13222.96,977.64 ; 13119.53,4501 13279.92,4501 ; 13169.46,3989.64 13169.46,3851.64 13307.46,3851.64 13307.46,3989.64 ; 13178.99,3979.64 13316.99,3979.64 ; 13375.46,2385.64 14218.46,2385.64 ; 13399.96,977.64 13399.96,1115.64 13537.96,1115.64 13537.96,977.64 ; 13405.7,1705.64 14187,1705.64 ; 13552.99,4009 14261.99,4009 ; 13593.46,3863 14252,3863 ; 13613.46,2208.64 14256.46,2208.64 ; 13693.46,2808.64 14161.46,2808.64 ; 13753.96,977.64 13753.96,1115.64 13891.96,1115.64 13891.96,977.64 ; 13952.53,4383 14112.92,4383 ; 13952.53,4501 14112.92,4501 ; 11438,1685 11576,1685 11576,1823 11438,1823 11438,1685 ; 11993.46,2966.64 12131.46,2966.64 12131.46,3104.64 11993.46,3104.64 11993.46,2966.64 ; 12144.46,1350.64 12282.46,1350.64 12282.46,1488.64 12144.46,1488.64 12144.46,1350.64 ; 12144.46,1506.64 12282.46,1506.64 12282.46,1644.64 12144.46,1644.64 12144.46,1506.64 ; 12144.46,1841.64 12282.46,1841.64 12282.46,1979.64 12144.46,1979.64 12144.46,1841.64 ; 12373.46,2364.64 12511.46,2364.64 12511.46,2502.64 12373.46,2502.64 12373.46,2364.64 ; 12374.46,2531.64 12512.46,2531.64 12512.46,2669.64 12374.46,2669.64 12374.46,2531.64 ; 12475.46,2808.64 12475.46,2946.64 12613.46,2946.64 12613.46,2808.64 12475.46,2808.64 ; 12504.46,2038.64 12642.46,2038.64 12642.46,2176.64 12504.46,2176.64 12504.46,2038.64 ; 12504.46,2208.64 12642.46,2208.64 12642.46,2346.64 12504.46,2346.64 12504.46,2208.64 ; 12844.46,1685.64 12982.46,1685.64 12982.46,1823.64 12844.46,1823.64 12844.46,1685.64 ; 12884.46,2364.64 13022.46,2364.64 13022.46,2502.64 12884.46,2502.64 12884.46,2364.64 ; 12884.46,2531.64 13022.46,2531.64 13022.46,2669.64 12884.46,2669.64 12884.46,2531.64 ; 12894.46,2966.64 13032.46,2966.64 13032.46,3104.64 12894.46,3104.64 12894.46,2966.64 ; 13001.99,4009 13001.99,4147 13139.99,4147 13139.99,4009 13001.99,4009 ; 13010.46,1350.64 13148.46,1350.64 13148.46,1488.64 13010.46,1488.64 13010.46,1350.64 ; 13096,2038 13234,2038 13234,2176 13096,2176 13096,2038 ; 13096.46,2208.64 13096.46,2346.64 13234.46,2346.64 13234.46,2208.64 13096.46,2208.64 ; 13217.46,2808.64 13355.46,2808.64 13355.46,2946.64 13217.46,2946.64 13217.46,2808.64 ; 13507,1843 13507,1981 13645,1981 13645,1843 13507,1843
  lines w20: 11290,50 11290,5460 14281,5460 14281,50 ; 11290,5322 14281,5322 ; 11299.53,4352.45 14290.99,4352.45
  text "DESIGN INFORMATION" at 12368.02,5361 h60
  text "MIN. TRACK WIDTH:" at 11723.46,5181 h60
  text "8" at 12819.7,5181 h60
  text "MIL" at 12974.46,5181 h60
  text "0.2" at 12759.7,5049 h60
  text "mm" at 12974.46,5049 h60
  text "MIN. VIA PAD SIZE:" at 11732.99,4907 h60
  text "24" at 12799.24,4907 h60
  text "MIL" at 12983.99,4907 h60
  text "0.05mm (2MIL)" at 12427.99,4765.29 h60
  text "EXTERNAL" at 13135.99,4761 h60
  text "IPC-D-275 CLASS 2 LEVEL C" at 11823.75,4643 h60
  text "MIL, HOLES" at 13311.99,4530.71 h60
  text "+/-" at 12919.53,4530 h60
  text "+/-" at 13773.53,4530 h60
  text "REGISTRATION TOLERANCES:" at 11403.75,4525 h60
  text "METAL" at 12603.53,4525 h60
  text "5" at 13179.73,4525 h60
  text "3" at 14012.73,4525 h60
  text "MIL" at 14128.99,4525 h60
  text "+/-" at 13773.53,4412 h60
  text "HOLE SIZE TOLERANCE (UNLESS OTHERWISE SPECIFIED):" at 11403.75,4407 h60
  text "3" at 14012.73,4407 h60
  text "MIL" at 14128.99,4407 h60
  text "FR-4 High Tg" at 12315.43,4057.21 h60
  text "OTHER" at 13237.99,4048.64 h60
  text "62 MIL (1.6mm) +/-10%" at 12060.56,3895.92 h60
  text "OTHER" at 13345.46,3891.64 h60
  text "ANSI IPC-6012 TYPE 3 CLASS 2" at 12420.48,3733.64 h60
  text "ANSI IPC-6012 TYPE 3 CLASS 2" at 12420.48,3420.64 h60
  text "OTHER +/-" at 12420.46,3262.13 h60
  text "DRILLING:" at 11319.46,3123.64 h60
  text "REFERENCE:" at 11394.23,3006.64 h60
  text "X" at 12042.46,3006.64 h60
  text "AS SHOWN" at 12229.46,3006.64 h60
  text "X" at 12943.46,3006.64 h60
  text "NC_DRILL FILES" at 13080.46,3006.64 h60
  text "PTH COPPER THICKNESS:" at 11394.23,2848.64 h60
  text "X" at 12524.46,2848.64 h60
  text "20-30 um" at 12661.46,2848.64 h60
  text "OTHER" at 13378.46,2848.64 h60
  text "BOARD FINISH:" at 11319.46,2689.64 h60
  text "SILKSCREEN:" at 11474.68,2571.64 h60
  text "X" at 12423.46,2571.64 h60
  text "TOP" at 12549.46,2571.64 h60
  text "X" at 12933.46,2571.64 h60
  text "BOTTOM" at 13060.46,2571.64 h60
  text "SILKSCREEN COLOR:" at 11474.68,2404.64 h60
  text "X" at 12422.42,2404.64 h60
  text "WHITE" at 12549.46,2404.64 h60
  text "OTHER" at 13060.46,2404.64 h60
  text "X" at 13139,2251 h60
  text "BLACK" at 13773.96,2248.44 h60
  text "GREEN" at 12680.46,2245.44 h60
  text "OTHER" at 13298.46,2245.44 h60
  text "SOLDER RESIST COLOR:" at 11474.68,2234.64 h60
  text "X" at 13142.5,2076.5 h60
  text "MATTE" at 12680.46,2075.44 h60
  text "SEMI-GLOSS" at 13298,2074.8 h60
  text "IMMERSION GOLD (ENIG)" at 12380.46,1886.92 h60
  text "ENEPIG" at 13718,1883.64 h60
  text "SURFACE FINISH:" at 11319.46,1882.64 h60
  text "X" at 12193.51,1882.64 h60
  text "IMM. TIN/SILVER OR EQUIV" at 11649,1725.64 h60
  text "OTHER" at 13080.46,1725.64 h60
  text "ARRAY/PANEL:" at 11319.46,1546.64 h60
  text "CUT AND TRIM PER M1 BOARD OUTLINE" at 12380.46,1542.35 h60
  text "N.C. ROUTE" at 12380.46,1390.64 h60
  text "X" at 13059.46,1390.64 h60
  text "V. SCORE" at 13246.46,1390.64 h60
  text "CERTIFICATION:" at 11319.46,1253.64 h60
  text "MATERIALS AND WORKMANSHIP FOR ALL PCBS" at 12044.46,1253.64 h60
  text "TO MEET OR EXCEED THE REQUIREMENTS OF:" at 12044.46,1155.64 h60
  text "X" at 11670.96,1019.13 h60
  text "ANSI IPC-A-600F CLASS ->" at 11809.96,1019.13 h60
  text "X" at 13449.02,1019.13 h60
  text "2" at 13567.96,1019.14 h60
  text ".Layer_Name" at 567,-1698.49 h60
M11 Gerber Information:
  lines w10: -302,-1770.17 6298,-1770.17 ; -302,-1566.83 6300,-1566.83 ; -302,-1363.5 -302,-1973.5 3703,-1973.5 6300,-1973.5 6300,-1363.5 -301.5,-1363.5 -301.5,-1973.5 1274,-1973.5 ; 2163,-1973.5 2163,-1363.5 ; 3430,-1566.83 3430,-1363.5 ; 4270,-1566.83 4270,-1363.5 ; 4892,-1980 4892,-1777.17
  text "ALL ARTWORK VIEWED FROM TOP SIDE" at -238.5,-1495.67 h60
  text "BOARD #:" at 2238,-1495.67 h60
  text ".PRJ_Number" at 2783.5,-1495.67 h60
  text "REV:" at 3628,-1495.67 h60
  text ".PCB_Rev" at 3919.5,-1495.67 h60
  text "SVN REV:" at 4466,-1495.67 h60
  text ".VersionControl_RevNumber" at 4972,-1495.67 h60
  text "LAYER NAME =" at -238.5,-1698.49 h60
  text "TID #:" at 2238,-1699 h60
  text ".TID" at 2783.5,-1699 h60
  text "PLOT NAME =" at -238.5,-1904.34 h60
  text ".plot_File_Name" at 567,-1904.34 h60
  text "GENERATED    :" at 2240,-1904.34 h60
  text ".Print_Date" at 3109.5,-1904.34 h60
  text ".Print_Time" at 3838.5,-1904.34 h60
  text "TEXAS INSTRUMENTS" at 5103,-1904.34 h60
M12 Stackup:
  drawing of 295 lines, arcs and shapes, not listed
  text "Layer" at 9787.84,6990 h60
  text "Name" at 10197.76,6990 h60
  text "Material" at 11137.5,6990 h60
  text "Thickness" at 11997.26,6990 h60
  text "Constant" at 12647.1,6990 h60
  text "Board Layer Stack" at 13216.96,6990 h60
  text "1" at 9787.84,6870 h60
  text "Top Overlay" at 10197.76,6870 h60
  text "2" at 9787.84,6750 h60
  text "Top Solder" at 10197.76,6750 h60
  text "Solder Resist" at 11137.5,6750 h60
  text "0.40mil" at 11997.26,6750 h60
  text "3.5" at 12647.1,6750 h60
  text "3" at 9787.84,6630 h60
  text "Top Layer" at 10197.76,6630 h60
  text "Copper" at 11137.5,6630 h60
  text "2.80mil" at 11997.26,6630 h60
  text "4" at 9787.84,6510 h60
  text "Dielectric 2" at 10197.76,6510 h60
  text "FR-4" at 11137.5,6510 h60
  text "10.00mil" at 11997.26,6510 h60
  text "4.2" at 12647.1,6510 h60
  text "5" at 9787.84,6390 h60
  text "Signal Layer 1" at 10197.76,6390 h60
  text "Copper" at 11137.5,6390 h60
  text "1.40mil" at 11997.26,6390 h60
  text "6" at 9787.84,6270 h60
  text "Dielectric 3" at 10197.76,6270 h60
  text "FR-4" at 11137.5,6270 h60
  text "10.00mil" at 11997.26,6270 h60
  text "4.2" at 12647.1,6270 h60
  text "7" at 9787.84,6150 h60
  text "Signal Layer 2" at 10197.76,6150 h60
  text "Copper" at 11137.5,6150 h60
  text "1.40mil" at 11997.26,6150 h60
  text "8" at 9787.84,6030 h60
  text "Dielectric1" at 10197.76,6030 h60
  text "FR-4" at 11137.5,6030 h60
  text "10.00mil" at 11997.26,6030 h60
  text "4.2" at 12647.1,6030 h60
  text "9" at 9787.84,5910 h60
  text "Bottom Layer" at 10197.76,5910 h60
  text "Copper" at 11137.5,5910 h60
  text "2.80mil" at 11997.26,5910 h60
  text "10" at 9787.84,5790 h60
  text "Bottom Solder" at 10197.76,5790 h60
  text "Solder Resist" at 11137.5,5790 h60
  text "0.40mil" at 11997.26,5790 h60
  text "3.5" at 12647.1,5790 h60
  text "11" at 9787.84,5670 h60
  text "Bottom Overlay" at 10197.76,5670 h60
  text ".Layer_Name" at 567,-1698.49 h60
M13 Component Bodies Top:
  text ".Layer_Name" at 567,-1698.49 h60
M14 Component Bodies Bottom:
  text ".Layer_Name" at 567,-1698.49 h60
M15 Courtyards Top:
  text ".Layer_Name" at 567,-1698.49 h60
M16 Courtyards Bottom:
  text ".Layer_Name" at 567,-1698.49 h60
M17 Embedded Cavity:
  text ".Layer_Name" at 567,-1698.49 h60
M18 Embedded Assembly:
  text ".Layer_Name" at 567,-1698.49 h60
M19 Embedded Keepout:
  text ".Layer_Name" at 567,-1698.49 h60

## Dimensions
-10,-1240 to 990,-1240 on M2 Board Dimensions
-0.01,-5.01 to 0,2610.02 on M2 Board Dimensions
-0.01,-5.01 to 4914.98,-10.01 on M2 Board Dimensions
